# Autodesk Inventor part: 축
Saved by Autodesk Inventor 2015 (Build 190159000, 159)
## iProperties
Created: 2026-07
Part Number: 축
Material: 일반
Document SubType Name: Modeling
Designer: user
Density: 1 g/cm^3
Appearance: 기본값
Author: user
Author: jhkim
Creation Date: 2026-07-01
Sending System: Autodesk Inventor 2027
Preprocessor: ST-DEVELOPER v20.1
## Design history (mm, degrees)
node "축1"
node "솔리드1"
node "기준1"
